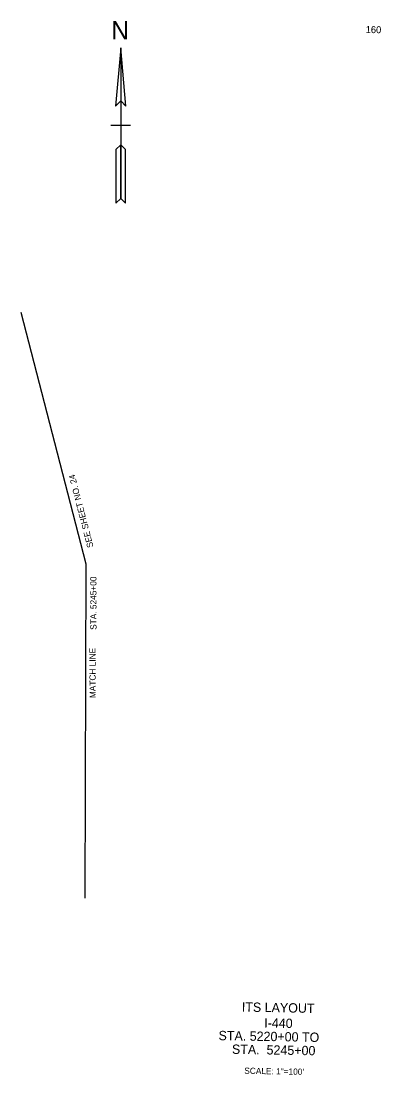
# Model space of a CAD drawing. Extents: x -200 to 1739885, y -325 to 650807.
# Drawn here: x 1739190 to 1739885, y 648771 to 650807 of the extents above; entities that cross this region are included whole.
import ezdxf

# ---------------------------------------------------------------- set-up
doc = ezdxf.new("R2010")
doc.units = 0
for name, color, linetype in [('DESIGN - CENTERLINE - Proposed Text', 7, 'Continuous'), ('DESIGN - SCRATCH - User 1', 7, 'Continuous'), ('DESIGN - SHEET - Corner Text', 7, 'Continuous'), ('ITS - CONST TEXT', 7, 'Continuous'), ('ITS - EXISITING WEATHER STATION', 7, 'Continuous'), ('ITS - EXISTING COMM CABLE', 7, 'Continuous'), ('ITS - EXISTING HAR', 7, 'Continuous')]:
    doc.layers.add(name, color=color, linetype=linetype)

msp = doc.modelspace()

# ---------------------------------------------------------------- linework, layer by layer
at = {"layer": 'DESIGN - CENTERLINE - Proposed Text'}
for p, q in [((1739382.2, 650605.1), (1739363.3, 650605.1)), ((1739401.1, 650605.1), (1739382.2, 650605.1))]:
    msp.add_line(p, q, dxfattribs=at)
msp.add_lwpolyline([(1739382.2, 650755.1), (1739372.4, 650642.5), (1739382.2, 650652.3), (1739392, 650642.5), (1739382.2, 650755.1), (1739382.2, 650464.2), (1739391.3, 650455.1), (1739391.3, 650558.6), (1739382.2, 650567.7), (1739373.1, 650558.6), (1739373.1, 650455.1), (1739382.2, 650464.2)], dxfattribs=at)
for points in [[(1739382.2, 650652.3), (1739392, 650642.5), (1739382.2, 650755.1)], [(1739373.1, 650455.1), (1739382.2, 650464.2), (1739382.2, 650567.7), (1739373.1, 650558.6)]]:
    msp.add_lwpolyline(points, close=True, dxfattribs=at)
at = {"layer": 'DESIGN - SCRATCH - User 1'}
msp.add_line((1739702.1, 648858), (1739702.1, 648858), dxfattribs=at)
msp.add_line((1739702.1, 648858), (1739702.1, 648858), dxfattribs=at)
at = {"layer": 'ITS - EXISITING WEATHER STATION'}
msp.add_line((1739702.1, 648858.1), (1739702.1, 648858.1), dxfattribs=at)
msp.add_line((1739702.1, 648858.1), (1739702.1, 648858.1), dxfattribs=at)
at = {"layer": 'ITS - EXISTING COMM CABLE'}
msp.add_lwpolyline([(1739313.4, 649112.4), (1739315.7, 649757.6), (1739189.7, 650243.7)], dxfattribs=at)

# ---------------------------------------------------------------- texts
at = {"layer": 'DESIGN - CENTERLINE - Proposed Text'}
msp.add_text('N', height=35.4, dxfattribs=at).set_placement((1739364.1, 650771.2))
at = {"layer": 'DESIGN - SHEET - Corner Text'}
msp.add_text('160', height=13.5, rotation=358.9359, dxfattribs=at).set_placement((1739855.5, 650783.6))
at = {"layer": 'ITS - CONST TEXT'}
msp.add_text('SCALE: 1"=100\'', height=12, rotation=358.936, dxfattribs=at).set_placement((1739621, 648773.5))
at = {"layer": 'ITS - EXISTING COMM CABLE'}
for s, rotation, p in [('SEE SHEET NO. 24 ', 104.5228, (1739329.8, 649791.3)), ('STA. 5245+00', 90.0438, (1739335.5, 649630.8)), ('MATCH LINE', 90.4116, (1739334.2, 649499))]:
    msp.add_text(s, height=12, rotation=rotation, dxfattribs=at).set_placement(p)
at = {"layer": 'ITS - EXISTING HAR'}
for s, p in [('ITS LAYOUT', (1739616.2, 648893.6)), ('I-440', (1739659.5, 648862.9)), ('STA. 5220+00 TO', (1739571.2, 648838.5)), ('STA.  5245+00', (1739597.1, 648812.1))]:
    msp.add_text(s, height=18, rotation=358.936, dxfattribs=at).set_placement(p)

doc.saveas('drawing.dxf')
